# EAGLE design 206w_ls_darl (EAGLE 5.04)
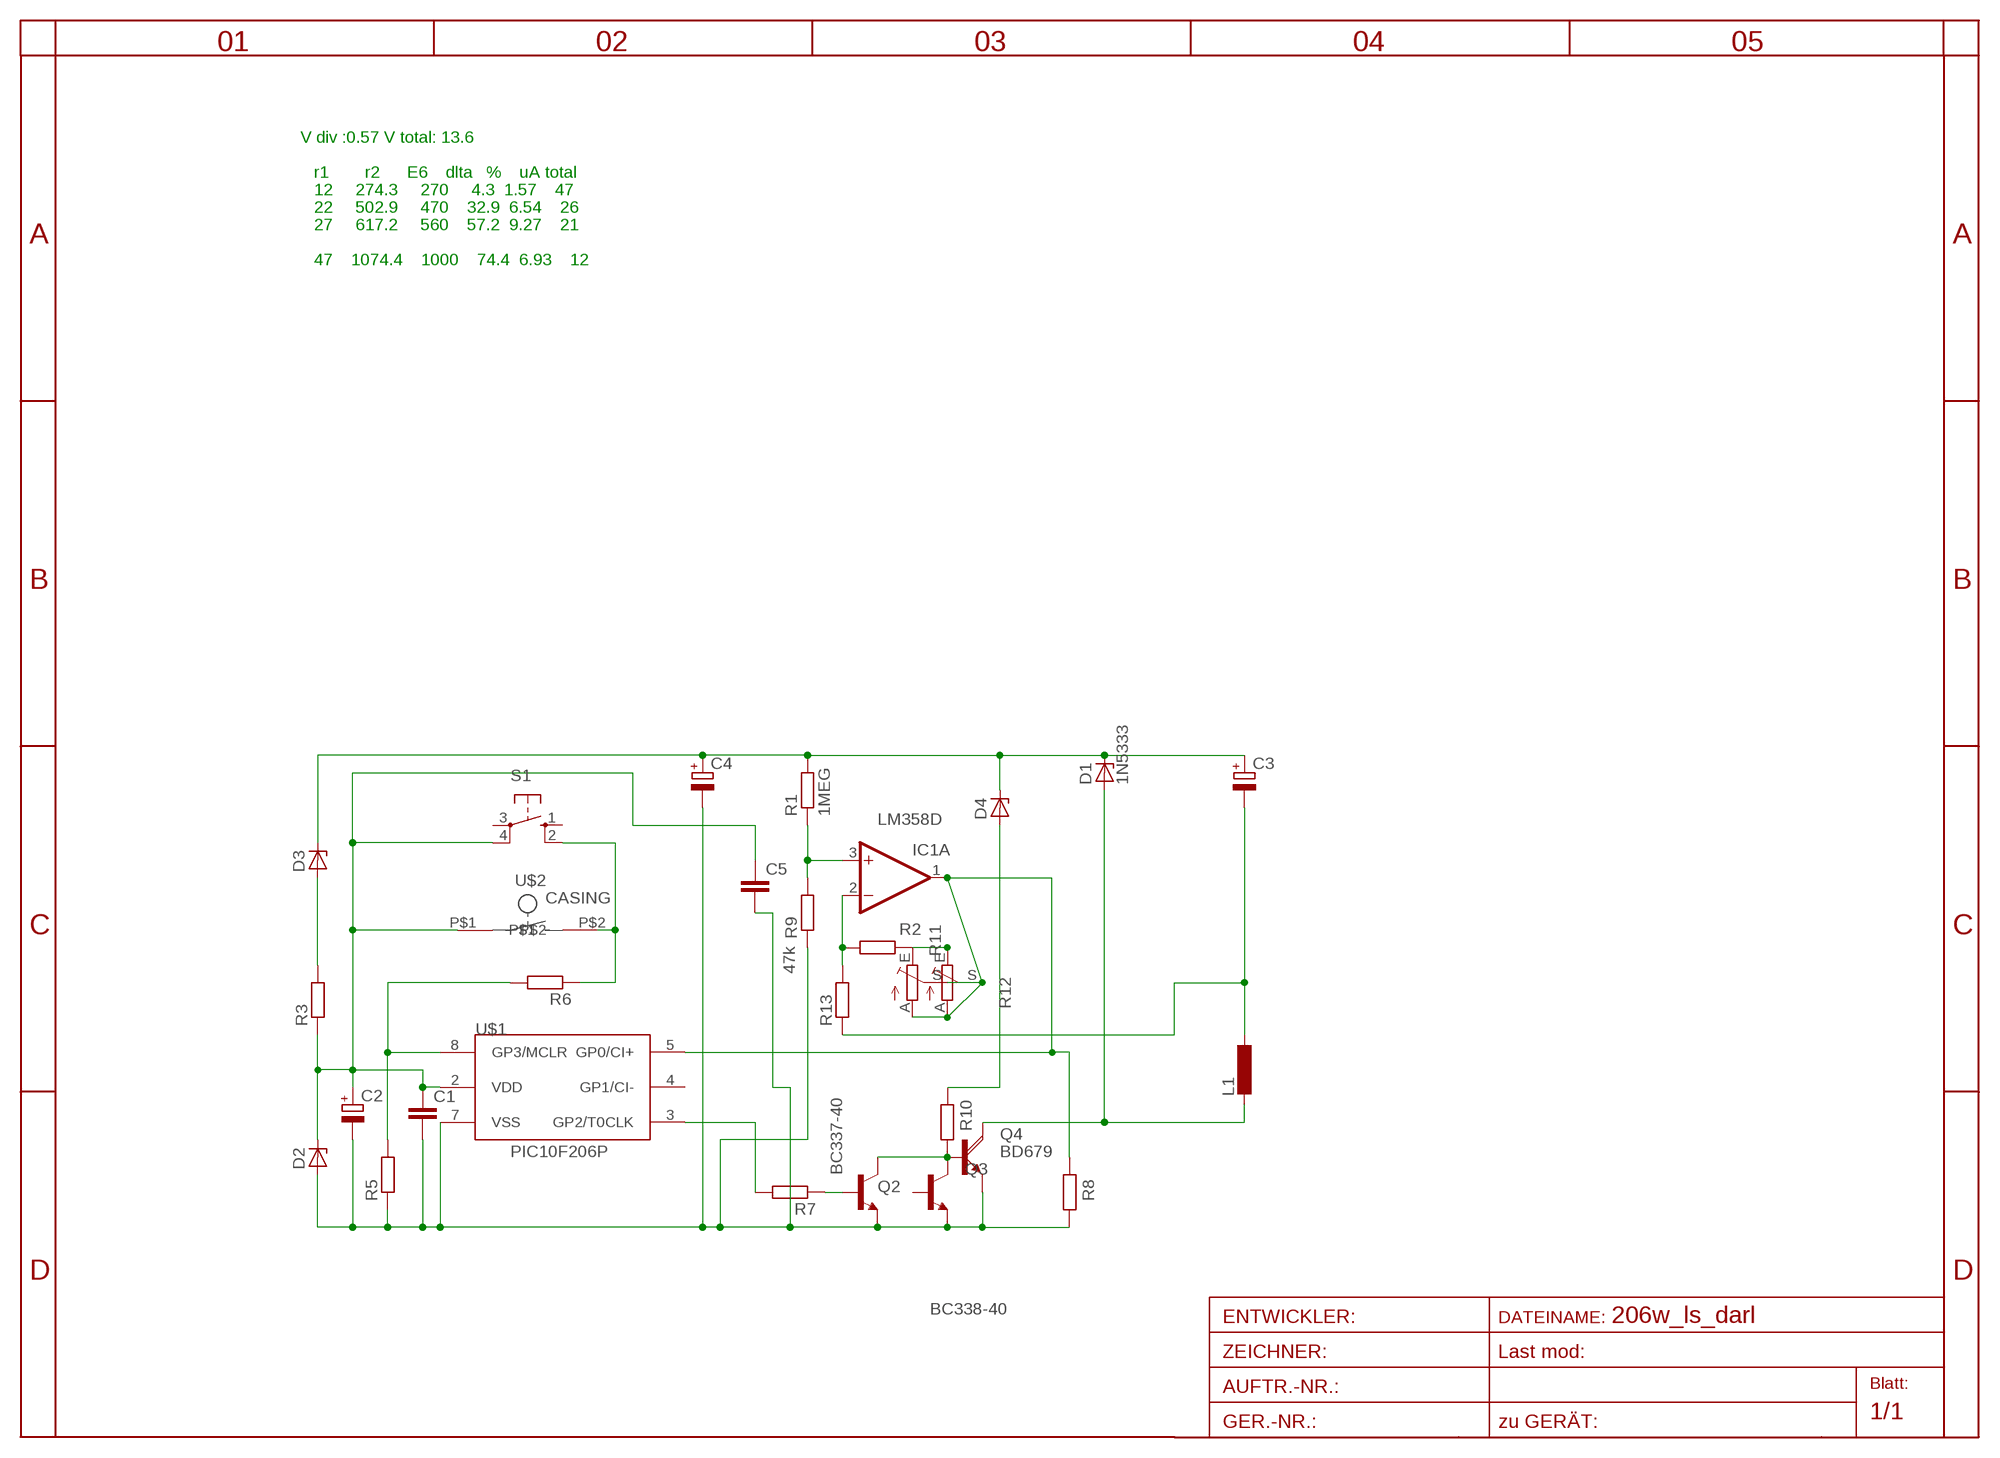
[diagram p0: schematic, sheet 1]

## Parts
C1  C-EU025-025X050  [C025-025X050]
C2  CPOL-EUE2.5-5  [E2,5-5]
C3  CPOL-EUE5-8.5  [E5-8,5]
C4  CPOL-EUE5-8.5  [E5-8,5]
C5  C-EU050-024X044  [C050-024X044]
D1  1N5333  [C1702-15]
D2  ZENER-DIODEZD-7.5  [ZDIO-7.5]
D3  ZENER-DIODEZD-7.5  [ZDIO-7.5]
D4  ZENER-DIODEZD-7.5  [ZDIO-7.5]
IC1  LM358D  [SO08]
L1  L-EU0207/10  [0207/10]
Q2  BC337-40  [TO92]
Q3  BC338-40  [TO92-EBC]
Q4  BD679  [TO126AV]
R1  1MEG  R-EU_0207/12  [0207/12]
R2  R-EU_0204/7  [0204/7]
R3  R-EU_0204/7  [0204/7]
R5  R-EU_0204/7  [0204/7]
R6  R-EU_0204/7  [0204/7]
R7  R-EU_0204/7  [0204/7]
R8  R-EU_0204/7  [0204/7]
R9  47k  R-EU_0204/7  [0204/7]
R10  R-EU_0204/7  [0204/7]
R11  TRIM_EU-CA6V  [CA6V]
R12  TRIM_EU-LI15  [LI15]
R13  R-EU_0207/30  [0207/30]
S1  10-XX  [B3F-10XX]
U$1  PIC10F206P  [DIL8]
U$2  CASING  [CASING]

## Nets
HOTSPOT: D1.A L1.2 Q4.C
N$1: IC1.1(A:OUT) R8.2 R11.A R11.S R12.A R12.S U$1.5(GP0/CI+)
N$2: R2.1 R11.E R12.E
N$3: D3.A R3.2
N$4: D4.A R10.2
N$5: R5.2 R6.2 U$1.8(GP3/MCLR)
N$7: R6.1 S1.2(S1) U$2.P$2
N$8: IC1.3(A:+IN) R1.1 R9.2
N$9: R7.2 U$1.3(GP2/T0CLK)
N$10: Q2.2(B) R7.1
N$11: Q2.3(C) Q3.C Q4.B R10.1
N$15: IC1.2(A:-IN) R2.2 R13.2
V60: C3.+ C4.+ D1.C D3.C D4.C R1.2
V+: C1.1 C2.+ C5.1 D2.C R3.1 S1.4(P1) U$1.2(VDD) U$2.P$1
V-: C1.2 C2.- C4.- C5.2 D2.A Q2.1(E) Q3.E Q4.E R5.1 R8.1 R9.1 U$1.7(VSS)
VOUT: C3.- L1.1 R13.1
Unconnected: IC1.5(B:+IN) IC1.6(B:-IN) IC1.7(B:OUT) Q3.B S1.1(S) S1.3(P) U$1.4(GP1/CI-)

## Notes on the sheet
- V div :0.57 V total: 13.6
- r1        r2      E6    dlta   %    uA total
- 12     274.3     270     4.3  1.57    47
- 22     502.9     470    32.9  6.54    26
- 27     617.2     560    57.2  9.27    21
- 47    1074.4    1000    74.4  6.93    12

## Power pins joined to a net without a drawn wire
V+: IC1.8(P:V+)
V-: IC1.4(P:V-)

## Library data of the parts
C1 C5 = rcl:C-EU: CAPACITOR, European symbol
C2-C4 = rcl:CPOL-EU: POLARIZED CAPACITOR, European symbol
D1 = diode-1:1N5333: Z DIODE
D2-D4 = diode-1:ZENER-DIODE: Z-Diode
IC1 = linear4:LM358: OP AMP
L1 = rcl:L-EU: INDUCTOR, European symbol
Q2 = transistor-npn:BC337*: NPN Transistor
Q3 = transistor-npn:BC338*: NPN Transistor
Q4 = transistor-power:BD679: NPN DARLINGTON TRANSISTOR
R1-R3 R5-R10 = rcl:R-EU_: RESISTOR, European symbol
R11 R12 = pot:TRIM_EU-: POTENTIOMETER
R13 = rcl-2:R-EU_: RESISTOR, European symbol
S1 = switch-omron:10-XX: OMRON SWITCH
U$1 = microchip-5:PIC10F2*: uPC nW 0,25/0,5k Program Flash memory Comparator
U$2 = button:CASING

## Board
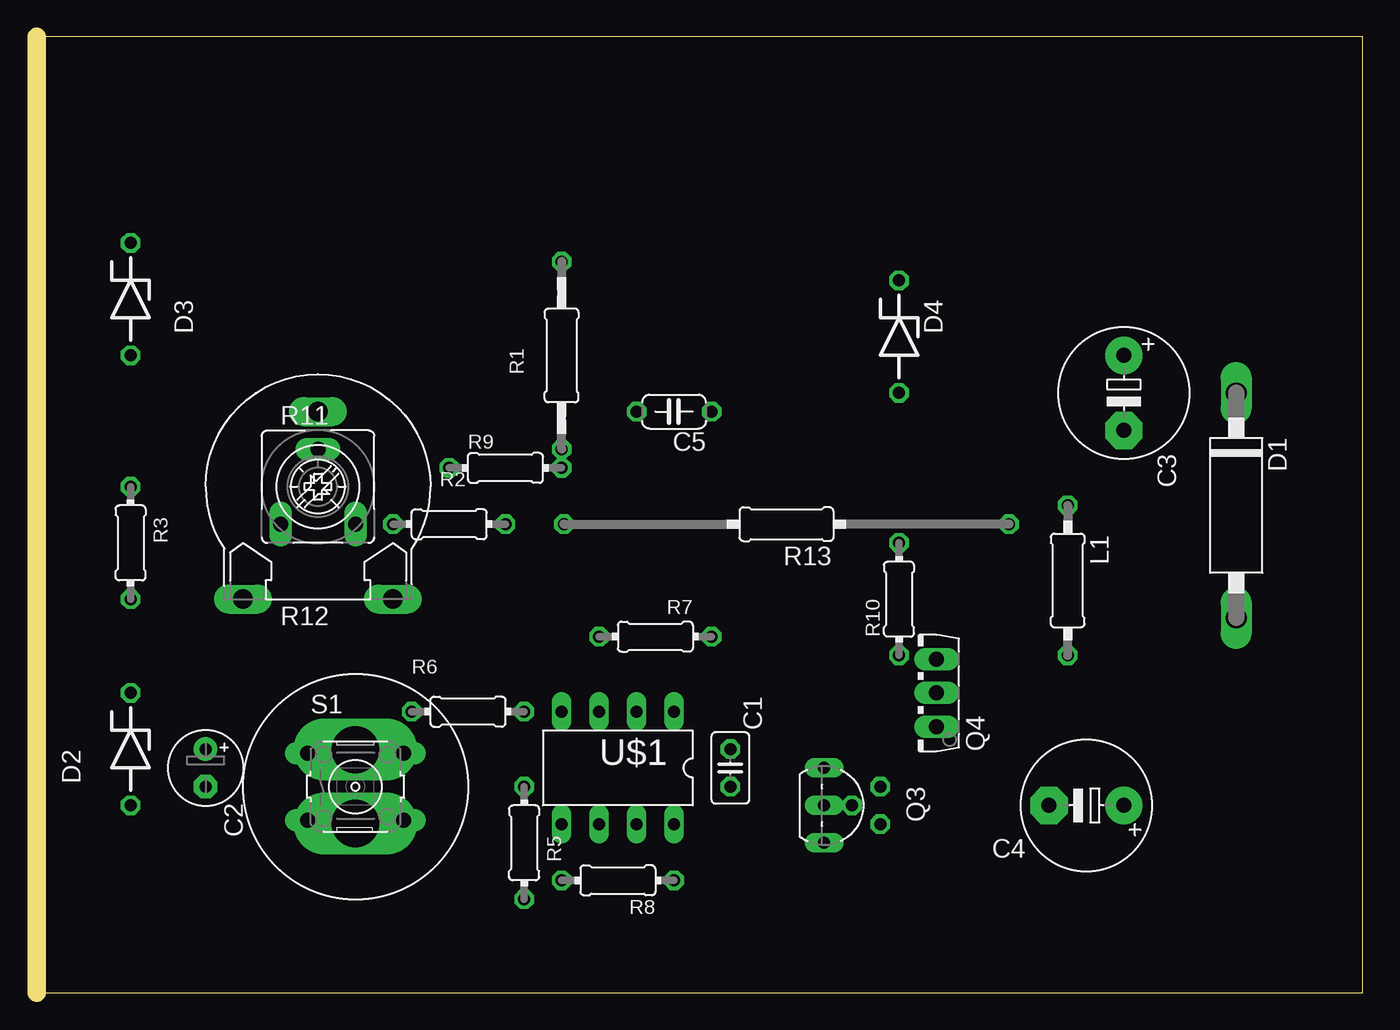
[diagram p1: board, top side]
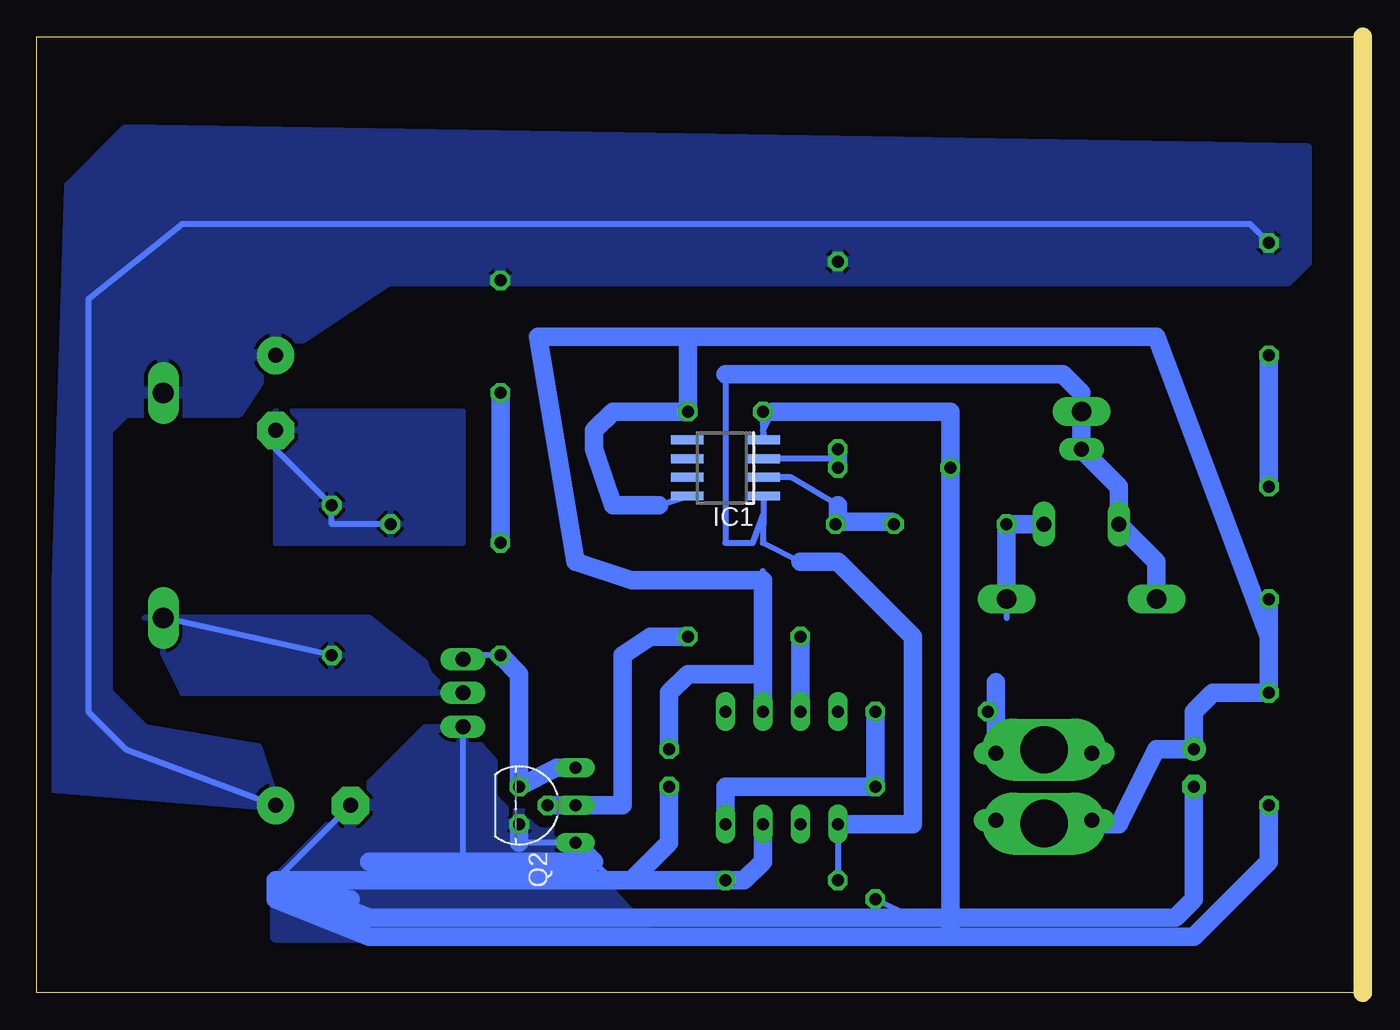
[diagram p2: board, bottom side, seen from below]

Size 89.84 x 64.76 mm. Coordinates in mm from the lower left corner, seen from the top.
Outline: 0,0 89.84,0 89.84,64.76 0,64.76 0,0
Copper layers (1*16): Top 0.035mm / dielectric 1.5mm / Bottom 0.035mm
Design rules "default": minimum track width 10mil, minimum drill 24mil, track to track 8mil, track to pad 8mil, pad to pad 8mil, via to via 8mil, smd to smd 8mil, copper to edge 40mil, drill to drill 8mil, minimum pad ring 10mil, minimum via ring 8mil, stop-mask expansion 4mil, vias tented up to drill 0mil, thermal gap 10mil

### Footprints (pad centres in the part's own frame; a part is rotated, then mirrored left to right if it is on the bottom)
C025-025X050 = drill 0.813 octagon: 1 -1.27,0; 2 1.27,0
E2,5-5 = drill 0.813 pad 1.6 round: + -1.27,0 | drill 0.813 pad 1.6 octagon: - 1.27,0
E5-8,5 = drill 1.016 pad 2.54 round: + -2.54,0 | drill 1.016 pad 2.54 octagon: - 2.54,0
C050-024X044 = drill 0.813 octagon: 1 -2.54,0; 2 2.54,0
C1702-15 = drill 1.397 long: A 7.62,0; C -7.62,0
ZDIO-7.5 = drill 0.813 octagon: A 3.81,0; C -3.81,0
SO08 = smd 0.6 x 2.2: 1 -1.905,-2.6; 2 -0.635,-2.6; 3 0.635,-2.6; 4 1.905,-2.6; 5 1.905,2.6; 6 0.635,2.6; 7 -0.635,2.6; 8 -1.905,2.6
0207/10 = drill 0.813 octagon: 1 -5.08,0; 2 5.08,0
TO92 = drill 0.813 octagon: 1 1.27,0; 2 0,1.905; 3 -1.27,0
TO92-EBC = drill 0.813 long: B 0,-1.27; C -2.54,-1.27; E 2.54,-1.27
TO126AV = drill 1.016 long: B 2.286,-1.27; C 0,-1.27; E -2.286,-1.27
0207/12 = drill 0.813 octagon: 1 -6.35,0; 2 6.35,0
0204/7 = drill 0.813 octagon: 1 -3.81,0; 2 3.81,0
CA6V = drill 1.016 long: A -2.54,-2.54; E 2.54,-2.54; S 0,2.54
LI15 = drill 1.321 long: A -5.08,-7.62; E 5.08,-7.62; S 0,5.08
0207/30 = drill 0.813 octagon: 1 -15.08,0; 2 15.08,0
B3F-10XX = drill 1.016 long: 1 -3.251,2.261; 2 3.251,2.261; 3 -3.251,-2.261; 4 3.251,-2.261
DIL8 = drill 0.813 long: 1 -3.81,-3.81; 2 -1.27,-3.81; 3 1.27,-3.81; 4 3.81,-3.81; 5 3.81,3.81; 6 1.27,3.81; 7 -1.27,3.81; 8 -3.81,3.81
CASING = drill 3.2 pad 3.81 long: P$1 -2.5,0; P$2 2.5,0

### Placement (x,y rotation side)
C1  46.99,15.24 270 top
C2  11.43,15.24 270 top
C3  73.66,40.64 270 top
C4  71.12,12.7 180 top
C5  43.18,39.37 180 top
D1  81.28,33.02 270 top
D2  6.35,16.51 270 top
D3  6.35,46.99 270 top
D4  58.42,44.45 270 top
IC1  43.18,35.56 90 bottom
L1  69.85,27.94 270 top
Q2  57.15,12.7 270 bottom
Q3  54.61,12.7 270 top
Q4  59.69,20.32 90 top
R1  35.56,43.18 90 top
R2  27.94,31.75 0 top
R3  6.35,30.48 90 top
R5  33.02,10.16 90 top
R6  29.21,19.05 0 top
R7  41.91,24.13 180 top
R8  39.37,7.62 180 top
R9  31.75,35.56 0 top
R10  58.42,26.67 90 top
R11  19.05,34.29 0 top
R12  19.05,34.29 0 top
R13  50.8,31.75 180 top
S1  21.59,13.97 0 top
U$1  39.37,15.24 180 top
U$2  21.59,13.97 90 top

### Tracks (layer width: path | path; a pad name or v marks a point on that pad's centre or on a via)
HOTSPOT
  Bottom 0.406: L1.2 D1.A
  pour Bottom (isolate 0.813, rank 3): 67.31,25.4 82.55,25.4 80.01,20.32 60.96,20.32
N$1
  Bottom 0.406: 43.18,41.91 43.18,30.48 41.32,30.48 40.64,32.34 40.64,31.75 | R12.S 19.05,40.64 | 38.1,29.21 40.64,30.48 40.64,31.75 | U$1.5 R8.2 | IC1.1 40.58,31.81 40.64,31.75
  Bottom 1.27: 43.18,41.91 20.32,41.91 19.05,40.64 | U$1.5 30.48,11.43 30.48,24.13 34.29,27.94 35.56,29.21 38.1,29.21 | R12.A 13.97,29.21 R11.A 16.51,34.29 R11.S R12.S
N$2
  Bottom 0.406: R12.E 24.13,25.4
  Bottom 1.27: R11.E R2.1 R12.E
N$3
  Bottom 1.27: R3.2 D3.A
N$4
  Bottom 1.27: R10.2 D4.A
N$5
  Bottom 1.27: U$1.8 43.18,13.97 R5.2 R6.2
N$7
  Bottom 0.406: 24.84,21.03 24.84,19.61 R6.1
  Bottom 1.27: 24.84,21.03 S1.2 21.83,16.23 U$2.P$2
N$8
  Bottom 0.406: IC1.3 36.2,36.2 R1.1
  Bottom 1.27: R9.2 R1.1
N$9
  Bottom 1.27: U$1.3 R7.2
N$10
  Bottom 1.27: R7.1 48.26,24.13 50.16,22.86 50.16,12.7 Q2.2
N$11
  Bottom 0.406: R10.1 60.71,22.86 Q4.B
  Bottom 1.27: Q3.C 54.61,15.24 Q2.3 57.15,21.59 R10.1
N$15
  Bottom 0.406: IC1.2 38.73,34.92 35.56,33.02 | 35.56,31.91 R13.2 | R2.2 31.91,31.91
  Bottom 1.27: 35.56,33.02 35.56,31.91 31.91,31.91
V60
  Bottom 0.406: C4.+ 83.82,16.51 86.36,19.05 86.36,46.99 80.01,52.07 7.62,52.07 D3.C
  pour Bottom (isolate 0.813, rank 5): 3.81,57.15 83.82,58.42 87.63,54.61 88.9,13.97 73.66,12.7 74.93,16.51 82.55,17.78 85.09,20.32 85.09,38.1 83.82,39.37 76.2,39.37 73.66,43.18 66.04,48.26 5.08,48.26 3.81,49.53
V+
  Bottom 0.406: 40.64,27.94 40.64,28.57 | 47.69,33.02 IC1.8
  Bottom 1.27: 24.56,11.43 16.51,11.43 13.97,16.51 C2.+ 11.43,19.05 10.16,20.32 D2.C 6.35,24.13 | 24.56,11.43 S1.4 | 24.56,11.43 21.63,11.43 U$2.P$1 | 40.64,21.59 U$1.2 | 40.64,21.59 40.64,27.94 49.53,27.94 53.34,29.21 55.88,44.45 45.72,44.45 | 45.72,44.45 13.97,44.45 6.35,24.13 | C1.1 46.99,20.32 45.72,21.59 40.64,21.59 | 6.35,24.13 R3.1 | 47.69,33.02 50.8,33.02 52.07,36.83 52.07,38.1 50.8,39.37 C5.1 45.72,44.45
V-
  Bottom 0.406: 40.01,39.37 40.64,38.1 IC1.4 40.64,38.8 C5.2 | 30.48,5.08 R5.1 | 49.53,7.62 50.8,7.62 52.07,8.89 | Q3.E 57.15,10.16 | 60.96,8.89 Q4.E | C4.- 73.66,7.62 72.39,6.35 71.25,6.35 71.03,6.57
  Bottom 1.27: D2.A 6.35,8.89 11.43,3.81 27.94,3.81 | 27.94,3.81 67.31,3.81 73.66,6.35 73.66,7.62 | 57.15,10.16 Q2.1 | C2.- 11.43,6.35 12.7,5.08 30.48,5.08 67.31,5.08 71.03,6.57 73.66,7.62 | 73.66,7.62 68.58,6.35 | U$1.7 40.64,8.89 41.91,7.62 R8.1 49.53,7.62 | 73.66,7.62 49.53,7.62 | Q3.E 52.07,8.89 60.96,8.89 67.31,8.89 | C1.2 46.99,10.16 49.53,7.62 | 40.01,39.37 27.94,39.37 R9.1 27.94,3.81
  pour Bottom (isolate 0.813): 60.96,17.78 63.5,17.78 73.66,7.62 73.66,3.81 48.26,3.81
VOUT
  Bottom 0.406: R13.1 69.85,31.75 L1.1 73.66,36.83 C3.-
  pour Bottom (isolate 0.813, rank 4): 60.96,39.37 73.66,39.37 73.66,30.48 60.96,30.48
